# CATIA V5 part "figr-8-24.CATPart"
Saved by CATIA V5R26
Part number: Part1
Bounding box of the stored display mesh (mm): x -50 to 50, y -62.5 to 62.5, z 0 to 10
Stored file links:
  D:\_Deepak\CATIA\CATIA V5-6R2016_Deepak\Resources\Part files\Partfiles\c08_catia_v5_6r2016_prt\figr-8-24.CATPart
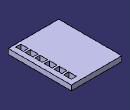
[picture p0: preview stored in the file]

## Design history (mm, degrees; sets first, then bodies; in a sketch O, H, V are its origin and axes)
Body1 (main body)
  Sketch1 on xy-plane, origin (0, 0, 0), H (1, 0, 0), V (0, 1, 0)
    line L1 (-50, 62.5) -> (50, 62.5)
    line L2 (50, 62.5) -> (50, -62.5)
    line L3 (50, -62.5) -> (-50, -62.5)
    line L4 (-50, -62.5) -> (-50, 62.5)
    axis line L5 (50, -62.5) -> (-50, 62.5)
    length L3 = 100
    length L2 = 125
    horizontal: L1 H, L3 H
    vertical: L2 V, L4 V
    midpoint: O L5
  Pad1: profile Sketch1, direction (0, 0, 1), length 10
  Sketch2 on face of Pad1, origin (0, 0, 10), H (1, 0, 0), V (0, 1, 0)
    line L1 (40, -57.5) -> (30, -57.5)
    line L2 (30, -57.5) -> (30, -42.5)
    line L3 (30, -42.5) -> (40, -42.5)
    line L4 (40, -42.5) -> (40, -57.5)
    reference projected line E1 (-50, -62.5) -> (50, -62.5) from edge [face of Pad1 | face of Pad1]
    reference projected line E2 (50, -62.5) -> (50, 62.5) from edge [face of Pad1 | face of Pad1]
    length L1 = 10
    length L4 = 15
    distance L1 E1 = 5
    distance L4 E2 = 10
    horizontal: L1 H, L3 H
    vertical: L2 V, L4 V
  Pocket1: profile Sketch2, direction (0, 0, -1), through (limit type 3)
  RectPattern1: of Pocket1, direction 1 instances 6, spacing 19, along edge [face of Pad1 | face of Pad1], direction 2 instances 6, spacing 15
